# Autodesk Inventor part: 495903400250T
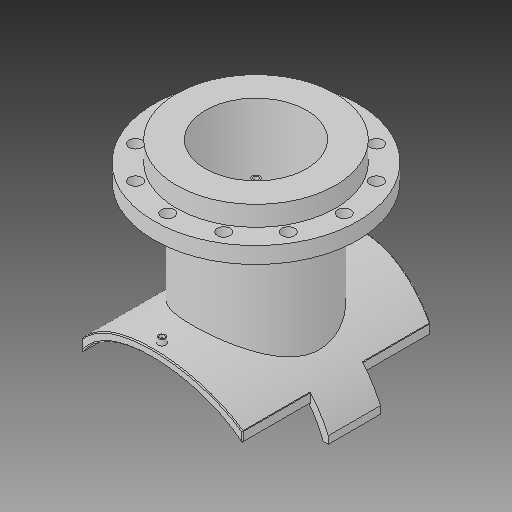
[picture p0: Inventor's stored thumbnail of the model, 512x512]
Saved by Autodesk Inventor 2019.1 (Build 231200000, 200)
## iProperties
Created: 2017-10
Part Number: 495903400250T
Material: Generic
Description: PLASSON FLANGED BRANCH SADDLE 400X250
Document SubType Name: Modeling
Designer: KIM
Mass: 2339.99 g
Surface Area: 3251.55 cm^2
Volume: 2339.99 cm^3
Density: 1 g/cm^3
Appearance: Default
Author: KIM
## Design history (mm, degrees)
derived "495904_495903.ipt"
feature "Solid1::495904_495903.ipt"
feature "Solid2::495904_495903.ipt"
tag "TaggingFeature1"
body "Solid1"
other parameters: "d1" = 15, "d2" = 324, "d4" = 0, "d6" = 105, "d7" = 0, "d12" = 225.6, "d13" = 14, "d14" = 189, "d16" = 5 deg, "d18" = 4, "d19" = 14, "d20" = 0, "d21" = 3, "d22" = 0, "d36" = 189, "d38" = 0, "d39" = 2, "d41" = 204, "d46" = 256, "d47" = 16, "d48" = 10.4, "d49" = 192.5, "d51" = 408, "d53" = 0, "d54" = 26, "d55" = 177.5, "d57" = 0, "d59" = 360 deg, "d61" = 33, "d63" = 0, "d66" = 275, "d67" = 15, "d68" = 137.5, "d70" = 0, "d71" = 2, "H_" = 275, "x_" = 15, "D_" = 16, "DN_" = 204, "t_" = 33, "s_" = 26, "Dp_" = 355
